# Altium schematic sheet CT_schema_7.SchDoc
size 274 x 160 mm
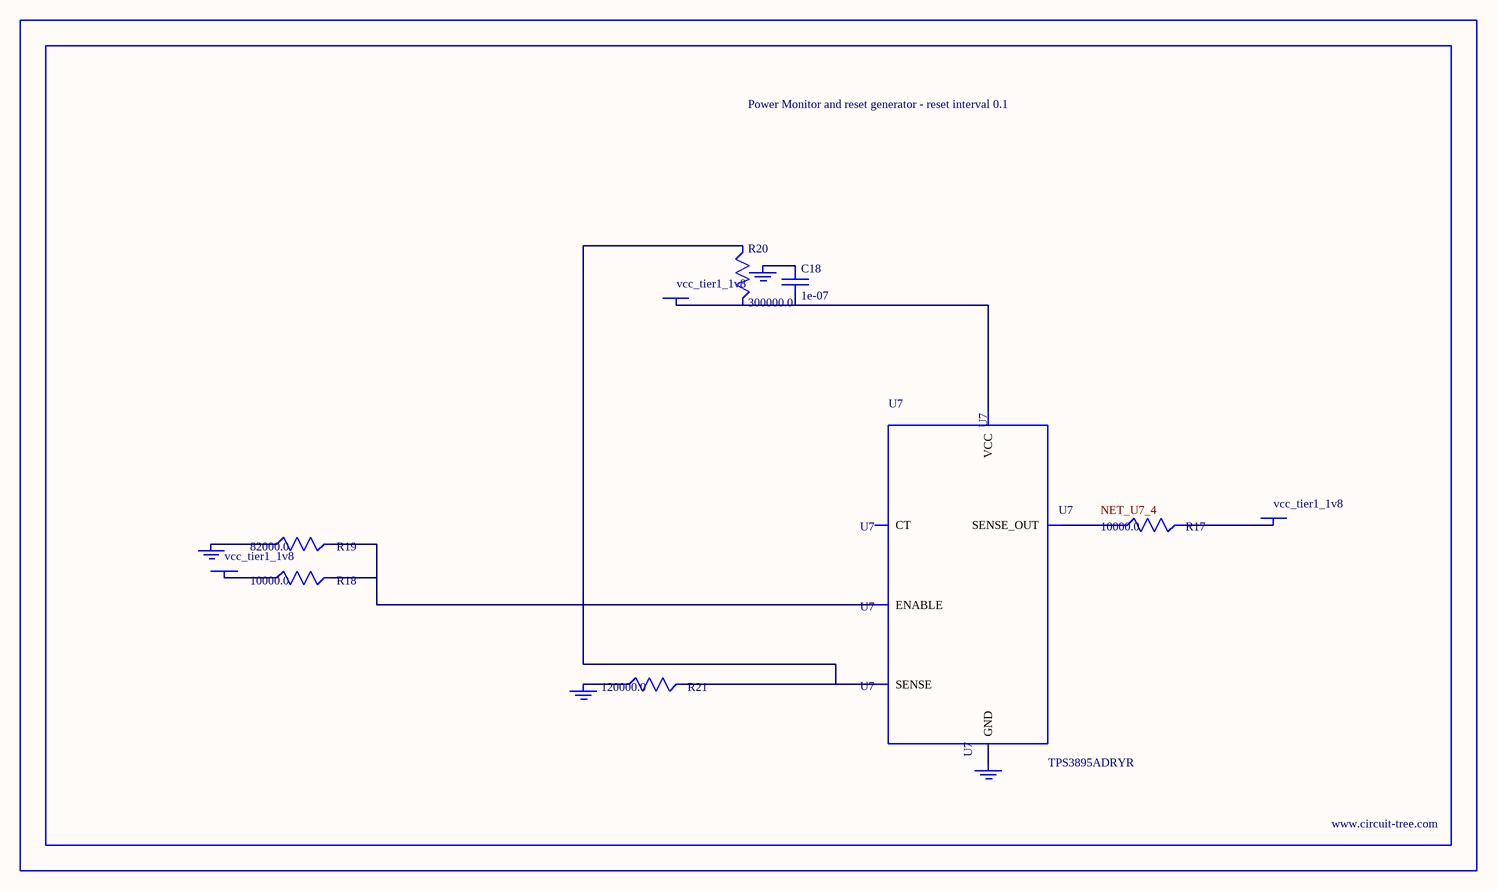
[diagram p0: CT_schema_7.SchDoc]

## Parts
BORDER6  (no value)
C18  1e-07  [C0402]
GND_INSTANCE_6_0  (no value)
GND_INSTANCE_6_1  (no value)
GND_INSTANCE_6_2  (no value)
GND_INSTANCE_6_3  (no value)
POWER_INSTANCE_6_0  vcc_tier1_1v8
POWER_INSTANCE_6_1  vcc_tier1_1v8
POWER_INSTANCE_6_2  vcc_tier1_1v8
R17  10000.0  [R0603]
R18  10000.0  [R0603]
R19  82000.0  [R0603]
R20  300000.0  [R0603]
R21  120000.0  [R0603]
U7  TPS3895ADRYR  [SON-6]

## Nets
NetC18_1: C18.1 GND_INSTANCE_6_2.0(GND)
NetC18_2: C18.2 POWER_INSTANCE_6_2.0(PWR) R20.2 U7.6(VCC)
NetGND_INSTANCE_6_0_0: GND_INSTANCE_6_0.0(GND) R19.1
NetGND_INSTANCE_6_1_0: GND_INSTANCE_6_1.0(GND) R21.1
NetGND_INSTANCE_6_3_0: GND_INSTANCE_6_3.0(GND) U7.2(GND)
NetPOWER_INSTANCE_6_0_0: POWER_INSTANCE_6_0.0(PWR) R18.1
NetPOWER_INSTANCE_6_1_0: POWER_INSTANCE_6_1.0(PWR) R17.2
NetR17_1: R17.1 U7.4(SENSE_OUT)
NetR18_2: R18.2 R19.2 U7.1(ENABLE)
NetR20_1: R20.1 R21.2 U7.3(SENSE)

Not connected (* = marked no-connect by the designer): U7 5(CT)

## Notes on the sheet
- Labels drawn without touching a wire or pin: NET_U7_4

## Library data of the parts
BORDER6 = BORDER_PAGE6
C18 = C0402C104K3RACTU
GND_INSTANCE_6_0-GND_INSTANCE_6_3 = GND
POWER_INSTANCE_6_0-POWER_INSTANCE_6_2 = PWR
R17 R18 = RC0603JR-0710KL
R19 = RC0603JR-0782KL
R20 = RC0603JR-07300KL
R21 = RC0603JR-07120KL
